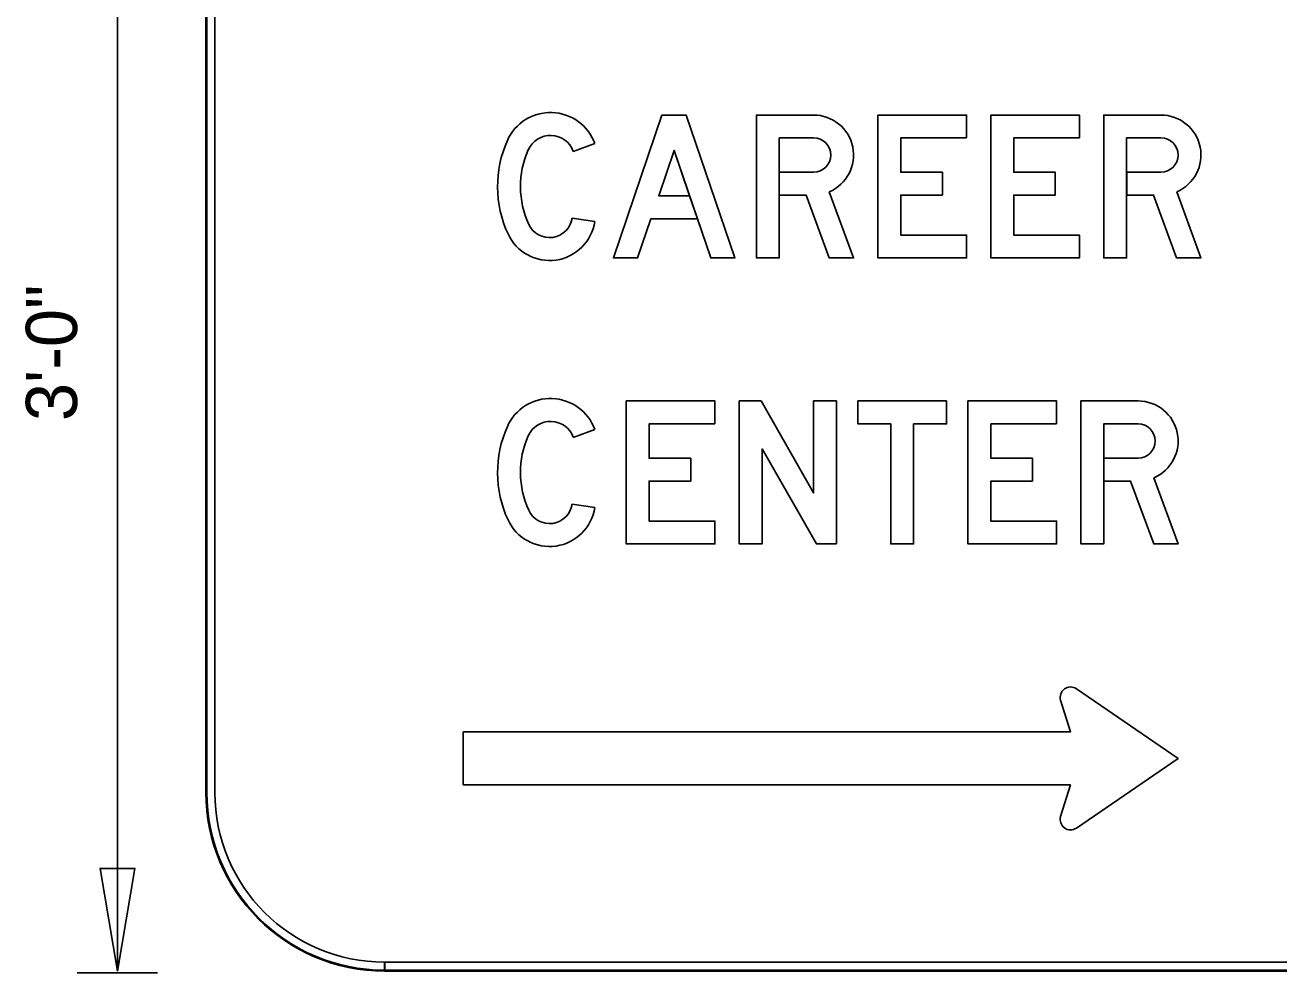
# Model space of a CAD drawing. Extents: x 0 to 770, y 0 to 495.
# Drawn here: x 614.7 to 700.4, y 221.5 to 286.3 of the extents above; entities that cross this region are included whole.
import ezdxf

# ---------------------------------------------------------------- set-up
doc = ezdxf.new("R2010")
doc.units = 0
for name, color, linetype in [('Dimension', 7, 'Continuous'), ('GSBWFill', 7, 'Continuous'), ('GSColorFill', 7, 'Continuous'), ('GSDims', 7, 'Continuous'), ('GSOutline', 7, 'Continuous'), ('TextStructures', 7, 'Continuous')]:
    doc.layers.add(name, color=color, linetype=linetype)

msp = doc.modelspace()

# ---------------------------------------------------------------- linework, layer by layer
at = {"layer": 'Dimension'}
msp.add_lwpolyline([(620.995, 221.626), (622.184, 228.642), (619.806, 228.642)], close=True, dxfattribs=at)
at = {"layer": 'GSBWFill'}
for p, q in [((627.04, 297.337), (627.04, 233.837)), ((627.04, 297.337), (627.04, 233.837)), ((627.65, 233.837), (627.65, 297.337)), ((666.214, 278.556), (668.559, 278.556)), ((689.953, 278.556), (692.298, 278.556)), ((653.612, 278.17), (652.143, 277.635)), ((652.066, 273.074), (653.612, 272.843)), ((688.39, 259.017), (690.735, 259.017)), ((653.612, 258.631), (652.143, 258.096)), ((652.066, 253.536), (653.612, 253.305)), ((639.251, 221.626), (639.251, 222.236)), ((702.751, 222.236), (639.257, 222.236)), ((639.257, 222.236), (639.257, 221.626)), ((639.251, 221.626), (702.751, 221.626)), ((639.257, 221.626), (702.751, 221.626))]:
    msp.add_line(p, q, dxfattribs=at)
for points in [[(654.882, 270.35), (658.203, 280.119), (659.864, 280.119), (663.186, 270.35), (661.535, 270.35), (659.034, 277.705), (657.977, 274.598), (660.09, 274.598), (660.621, 273.035), (657.446, 273.035), (656.533, 270.35)], [(679.012, 278.556), (674.518, 278.556), (674.518, 276.211), (677.359, 276.211), (677.359, 274.648), (674.518, 274.648), (674.518, 271.913), (679.012, 271.913), (679.012, 270.35), (672.955, 270.35), (672.955, 280.119), (679.012, 280.119)], [(686.73, 278.556), (682.236, 278.556), (682.236, 276.211), (685.076, 276.211), (685.076, 274.648), (682.236, 274.648), (682.236, 271.913), (686.73, 271.913), (686.73, 270.35), (680.673, 270.35), (680.673, 280.119), (686.73, 280.119)], [(661.818, 259.017), (657.324, 259.017), (657.324, 256.673), (660.165, 256.673), (660.165, 255.11), (657.324, 255.11), (657.324, 252.374), (661.818, 252.374), (661.818, 250.811), (655.761, 250.811), (655.761, 260.58), (661.818, 260.58)], [(670.122, 250.811), (670.122, 260.58), (668.559, 260.58), (668.559, 254.304), (664.972, 260.58), (663.479, 260.58), (663.479, 250.811), (665.042, 250.811), (665.042, 257.308), (668.754, 250.811)], [(677.644, 260.58), (677.644, 259.017), (675.397, 259.017), (675.397, 250.811), (673.834, 250.811), (673.834, 259.017), (671.587, 259.017), (671.587, 260.58)], [(685.166, 259.017), (680.673, 259.017), (680.673, 256.673), (683.513, 256.673), (683.513, 255.11), (680.673, 255.11), (680.673, 252.374), (685.166, 252.374), (685.166, 250.811), (679.11, 250.811), (679.11, 260.58), (685.166, 260.58)]]:
    msp.add_lwpolyline(points, close=True, dxfattribs=at)
for points in [[(668.559, 280.119), (664.651, 280.119), (664.651, 270.35), (666.214, 270.35), (666.214, 278.556)], [(692.298, 280.119), (688.39, 280.119), (688.39, 270.35), (689.953, 270.35), (689.953, 278.556)], [(668.559, 276.211), (666.215, 276.211), (666.215, 274.648), (668.049, 274.648), (669.629, 270.35), (671.294, 270.35), (669.633, 274.868)], [(692.298, 276.211), (689.954, 276.211), (689.954, 274.648), (691.788, 274.648), (693.368, 270.35), (695.033, 270.35), (693.373, 274.868)], [(690.735, 260.58), (686.827, 260.58), (686.827, 250.811), (688.39, 250.811), (688.39, 259.017)], [(690.735, 256.673), (688.391, 256.673), (688.391, 255.11), (690.225, 255.11), (691.805, 250.811), (693.47, 250.811), (691.81, 255.33)], [(686.517, 231.396), (693.47, 236.157), (686.517, 240.919)], [(685.444, 240.13), (686.107, 237.97), (644.624, 237.97)], [(644.624, 237.97), (644.624, 234.344), (686.107, 234.344), (685.444, 232.184)]]:
    msp.add_lwpolyline(points, dxfattribs=at)
for centre, radius, start, end in [((650.583, 277.066), 3.224, 20.02358, 155.94529), ((668.559, 277.383), 2.735, 293.1324, 90), ((692.298, 277.383), 2.735, 293.1324, 90), ((650.583, 277.066), 1.661, 20.02358, 155.94529), ((668.559, 277.383), 1.172, 270, 90), ((692.298, 277.383), 1.172, 270, 90), ((654.686, 275.234), 7.718, 155.9453, 204.84802), ((654.686, 275.234), 6.155, 155.94529, 204.84802), ((650.52, 273.305), 3.126, 204.84802, 351.50601), ((650.52, 273.305), 1.563, 204.84802, 351.50601), ((650.583, 257.528), 3.224, 20.02358, 155.94529), ((690.735, 257.845), 2.735, 293.1324, 90), ((654.686, 255.696), 7.718, 155.9453, 204.84802), ((650.583, 257.528), 1.661, 20.02358, 155.94529), ((690.735, 257.845), 1.172, 270, 90), ((654.686, 255.696), 6.155, 155.94529, 204.84802), ((650.52, 253.766), 3.126, 204.84802, 351.50601), ((650.52, 253.766), 1.563, 204.84802, 351.50601), ((686.118, 240.337), 0.705, 55.60026, 197.05729), ((639.251, 233.837), 12.212, 180, 270), ((639.251, 233.837), 12.212, 180, 270), ((639.251, 233.837), 11.601, 180, 270), ((686.118, 231.978), 0.705, 162.94271, 304.39974)]:
    msp.add_arc(centre, radius, start, end, dxfattribs=at)
at = {"layer": 'GSColorFill'}
for p, q in [((627.04, 297.337), (627.04, 233.837)), ((627.04, 297.337), (627.04, 233.837)), ((627.04, 297.337), (627.04, 233.837)), ((627.101, 233.837), (627.101, 297.337)), ((627.65, 233.837), (627.65, 297.337)), ((666.214, 278.556), (668.559, 278.556)), ((689.953, 278.556), (692.298, 278.556)), ((653.612, 278.17), (652.143, 277.635)), ((652.066, 273.074), (653.612, 272.843)), ((688.39, 259.017), (690.735, 259.017)), ((653.612, 258.631), (652.143, 258.096)), ((652.066, 253.536), (653.612, 253.305)), ((639.251, 221.626), (639.251, 222.236)), ((702.751, 222.236), (639.257, 222.236)), ((639.257, 222.236), (639.257, 221.626)), ((639.251, 221.626), (639.251, 221.687)), ((639.251, 221.626), (702.751, 221.626)), ((702.751, 221.687), (639.252, 221.687)), ((639.252, 221.687), (639.252, 221.626)), ((639.252, 221.626), (702.751, 221.626)), ((639.257, 221.626), (702.751, 221.626))]:
    msp.add_line(p, q, dxfattribs=at)
for points in [[(654.882, 270.35), (658.203, 280.119), (659.864, 280.119), (663.186, 270.35), (661.535, 270.35), (659.034, 277.705), (657.977, 274.598), (660.09, 274.598), (660.621, 273.035), (657.446, 273.035), (656.533, 270.35)], [(679.012, 278.556), (674.518, 278.556), (674.518, 276.211), (677.359, 276.211), (677.359, 274.648), (674.518, 274.648), (674.518, 271.913), (679.012, 271.913), (679.012, 270.35), (672.955, 270.35), (672.955, 280.119), (679.012, 280.119)], [(686.73, 278.556), (682.236, 278.556), (682.236, 276.211), (685.076, 276.211), (685.076, 274.648), (682.236, 274.648), (682.236, 271.913), (686.73, 271.913), (686.73, 270.35), (680.673, 270.35), (680.673, 280.119), (686.73, 280.119)], [(661.818, 259.017), (657.324, 259.017), (657.324, 256.673), (660.165, 256.673), (660.165, 255.11), (657.324, 255.11), (657.324, 252.374), (661.818, 252.374), (661.818, 250.811), (655.761, 250.811), (655.761, 260.58), (661.818, 260.58)], [(670.122, 250.811), (670.122, 260.58), (668.559, 260.58), (668.559, 254.304), (664.972, 260.58), (663.479, 260.58), (663.479, 250.811), (665.042, 250.811), (665.042, 257.308), (668.754, 250.811)], [(677.644, 260.58), (677.644, 259.017), (675.397, 259.017), (675.397, 250.811), (673.834, 250.811), (673.834, 259.017), (671.587, 259.017), (671.587, 260.58)], [(685.166, 259.017), (680.673, 259.017), (680.673, 256.673), (683.513, 256.673), (683.513, 255.11), (680.673, 255.11), (680.673, 252.374), (685.166, 252.374), (685.166, 250.811), (679.11, 250.811), (679.11, 260.58), (685.166, 260.58)]]:
    msp.add_lwpolyline(points, close=True, dxfattribs=at)
for points in [[(668.559, 280.119), (664.651, 280.119), (664.651, 270.35), (666.214, 270.35), (666.214, 278.556)], [(692.298, 280.119), (688.39, 280.119), (688.39, 270.35), (689.953, 270.35), (689.953, 278.556)], [(668.559, 276.211), (666.215, 276.211), (666.215, 274.648), (668.049, 274.648), (669.629, 270.35), (671.294, 270.35), (669.633, 274.868)], [(692.298, 276.211), (689.954, 276.211), (689.954, 274.648), (691.788, 274.648), (693.368, 270.35), (695.033, 270.35), (693.373, 274.868)], [(690.735, 260.58), (686.827, 260.58), (686.827, 250.811), (688.39, 250.811), (688.39, 259.017)], [(690.735, 256.673), (688.391, 256.673), (688.391, 255.11), (690.225, 255.11), (691.805, 250.811), (693.47, 250.811), (691.81, 255.33)], [(686.517, 231.396), (693.47, 236.157), (686.517, 240.919)], [(685.444, 240.13), (686.107, 237.97), (644.624, 237.97)], [(644.624, 237.97), (644.624, 234.344), (686.107, 234.344), (685.444, 232.184)]]:
    msp.add_lwpolyline(points, dxfattribs=at)
for centre, radius, start, end in [((650.583, 277.066), 3.224, 20.02358, 155.94529), ((668.559, 277.383), 2.735, 293.1324, 90), ((692.298, 277.383), 2.735, 293.1324, 90), ((650.583, 277.066), 1.661, 20.02358, 155.94529), ((668.559, 277.383), 1.172, 270, 90), ((692.298, 277.383), 1.172, 270, 90), ((654.686, 275.234), 7.718, 155.9453, 204.84802), ((654.686, 275.234), 6.155, 155.94529, 204.84802), ((650.52, 273.305), 3.126, 204.84802, 351.50601), ((650.52, 273.305), 1.563, 204.84802, 351.50601), ((650.583, 257.528), 3.224, 20.02358, 155.94529), ((690.735, 257.845), 2.735, 293.1324, 90), ((654.686, 255.696), 7.718, 155.9453, 204.84802), ((650.583, 257.528), 1.661, 20.02358, 155.94529), ((690.735, 257.845), 1.172, 270, 90), ((654.686, 255.696), 6.155, 155.94529, 204.84802), ((650.52, 253.766), 3.126, 204.84802, 351.50601), ((650.52, 253.766), 1.563, 204.84802, 351.50601), ((686.118, 240.337), 0.705, 55.60026, 197.05729), ((639.251, 233.837), 12.212, 180, 270), ((639.251, 233.837), 12.212, 180, 270), ((639.251, 233.837), 12.212, 180, 270), ((639.251, 233.837), 12.15, 180, 270), ((639.251, 233.837), 11.601, 180, 270), ((686.118, 231.978), 0.705, 162.94271, 304.39974)]:
    msp.add_arc(centre, radius, start, end, dxfattribs=at)
at = {"layer": 'GSDims'}
for p, q in [((620.995, 221.626), (620.995, 309.549)), ((623.742, 221.503), (618.247, 221.503))]:
    msp.add_line(p, q, dxfattribs=at)
at = {"layer": 'GSOutline'}
for p, q in [((627.04, 297.337), (627.04, 233.837)), ((627.04, 297.337), (627.04, 233.837)), ((627.65, 297.337), (627.65, 233.837)), ((653.612, 278.17), (652.143, 277.635)), ((671.294, 270.35), (669.633, 274.868)), ((695.033, 270.35), (693.373, 274.868)), ((652.066, 273.074), (653.612, 272.843)), ((653.612, 258.631), (652.143, 258.096)), ((693.47, 250.811), (691.81, 255.33)), ((652.066, 253.536), (653.612, 253.305)), ((639.251, 222.236), (702.751, 222.236)), ((639.251, 221.626), (702.751, 221.626)), ((639.251, 221.626), (702.751, 221.626))]:
    msp.add_line(p, q, dxfattribs=at)
for points in [[(657.446, 273.035), (656.533, 270.35), (654.882, 270.35), (658.203, 280.119), (659.864, 280.119), (663.186, 270.35), (661.535, 270.35), (660.622, 273.035)], [(679.012, 278.556), (674.518, 278.556), (674.518, 276.211), (677.359, 276.211), (677.359, 274.648), (674.518, 274.648), (674.518, 271.913), (679.012, 271.913), (679.012, 270.35), (672.955, 270.35), (672.955, 280.119), (679.012, 280.119)], [(686.73, 278.556), (682.236, 278.556), (682.236, 276.211), (685.076, 276.211), (685.076, 274.648), (682.236, 274.648), (682.236, 271.913), (686.73, 271.913), (686.73, 270.35), (680.673, 270.35), (680.673, 280.119), (686.73, 280.119)], [(657.977, 274.598), (660.09, 274.598), (659.034, 277.705)], [(661.818, 259.017), (657.324, 259.017), (657.324, 256.673), (660.165, 256.673), (660.165, 255.11), (657.324, 255.11), (657.324, 252.374), (661.818, 252.374), (661.818, 250.811), (655.761, 250.811), (655.761, 260.58), (661.818, 260.58)], [(670.122, 250.811), (670.122, 260.58), (668.559, 260.58), (668.559, 254.304), (664.972, 260.58), (663.479, 260.58), (663.479, 250.811), (665.042, 250.811), (665.042, 257.308), (668.754, 250.811)], [(677.644, 260.58), (677.644, 259.017), (675.397, 259.017), (675.397, 250.811), (673.834, 250.811), (673.834, 259.017), (671.587, 259.017), (671.587, 260.58)], [(685.166, 259.017), (680.673, 259.017), (680.673, 256.673), (683.513, 256.673), (683.513, 255.11), (680.673, 255.11), (680.673, 252.374), (685.166, 252.374), (685.166, 250.811), (679.11, 250.811), (679.11, 260.58), (685.166, 260.58)]]:
    msp.add_lwpolyline(points, close=True, dxfattribs=at)
for points in [[(668.559, 280.119), (664.651, 280.119), (664.651, 270.35), (666.214, 270.35), (666.214, 274.648), (668.049, 274.648), (669.629, 270.35), (671.294, 270.35)], [(692.298, 280.119), (688.39, 280.119), (688.39, 270.35), (689.953, 270.35), (689.953, 274.648), (691.788, 274.648), (693.368, 270.35), (695.033, 270.35)], [(668.559, 276.211), (666.214, 276.211), (666.214, 278.556), (668.559, 278.556)], [(692.298, 276.211), (689.953, 276.211), (689.953, 278.556), (692.298, 278.556)], [(690.735, 260.58), (686.827, 260.58), (686.827, 250.811), (688.39, 250.811), (688.39, 255.11), (690.225, 255.11), (691.805, 250.811), (693.47, 250.811)], [(690.735, 256.673), (688.39, 256.673), (688.39, 259.017), (690.735, 259.017)], [(686.517, 231.396), (693.47, 236.157), (686.517, 240.919)], [(685.444, 240.13), (686.107, 237.97), (644.624, 237.97)], [(644.624, 237.97), (644.624, 234.344), (686.107, 234.344), (685.444, 232.184)]]:
    msp.add_lwpolyline(points, dxfattribs=at)
for centre, radius, start, end in [((650.583, 277.066), 3.224, 20.02358, 155.94529), ((668.559, 277.383), 2.735, 293.1324, 90), ((692.298, 277.383), 2.735, 293.1324, 90), ((650.583, 277.066), 1.661, 20.02358, 155.94529), ((668.559, 277.383), 1.172, 270, 90), ((692.298, 277.383), 1.172, 270, 90), ((654.686, 275.234), 7.718, 155.9453, 204.84802), ((654.686, 275.234), 6.155, 155.94529, 204.84802), ((650.52, 273.305), 3.126, 204.84802, 351.50601), ((650.52, 273.305), 1.563, 204.84802, 351.50601), ((650.583, 257.528), 3.224, 20.02358, 155.94529), ((690.735, 257.845), 2.735, 293.1324, 90), ((654.686, 255.696), 7.718, 155.9453, 204.84802), ((650.583, 257.528), 1.661, 20.02358, 155.94529), ((690.735, 257.845), 1.172, 270, 90), ((654.686, 255.696), 6.155, 155.94529, 204.84802), ((650.52, 253.766), 3.126, 204.84802, 351.50601), ((650.52, 253.766), 1.563, 204.84802, 351.50601), ((686.118, 240.337), 0.705, 55.60026, 197.05729), ((639.251, 233.837), 12.212, 180, 270), ((639.251, 233.837), 12.212, 180, 270), ((639.251, 233.837), 11.601, 180, 270), ((686.118, 231.978), 0.705, 162.94271, 304.39974)]:
    msp.add_arc(centre, radius, start, end, dxfattribs=at)

# ---------------------------------------------------------------- texts
at = {"layer": 'TextStructures'}
msp.add_text('3\'-0"', height=3.5, rotation=90, dxfattribs=at).set_placement((618.235, 259.209))

doc.saveas('drawing.dxf')
